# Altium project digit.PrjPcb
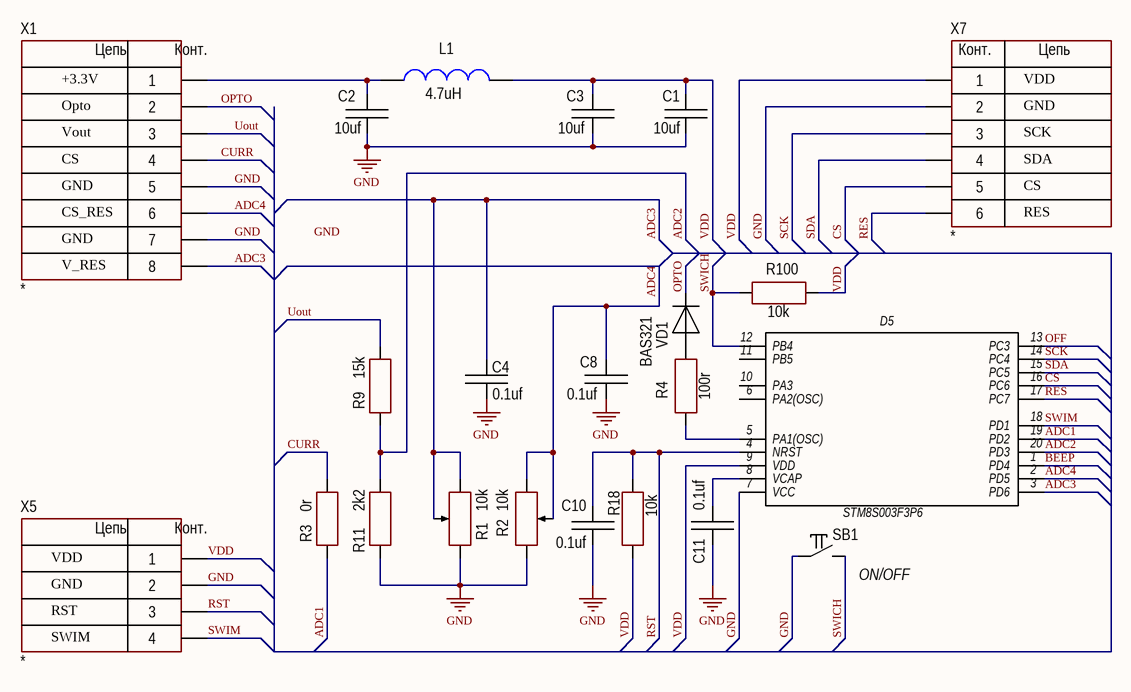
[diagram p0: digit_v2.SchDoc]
2 sheets, 25 parts. Net scope: global (net labels, ports and power ports of the same name join across sheets).
Board file: LCD.PcbDoc
Sheets:
  digit_v2.SchDoc
  LCD.SchDoc

## Sheet digit_v2.SchDoc
size 297 x 209 mm; Address1: Address1; Address2: Address2; Address3: Address3; Address4: Address4; DocumentNumber: АБВГ.123456.001 Э3; SheetNumber: 1; Scale: 1:1; DocumentType: Схема электрическая принципиальная; FirstReferrence: АБВГ.123456.001

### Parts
C1  10uf  [CH1206C]
C2  10uf  [CH1206C]
C3  10uf  [CH1206C]
C4  0.1uf  [CH0805C]
C8  0.1uf  [CH0805C]
C10  0.1uf  [CH0805C]
C11  0.1uf  [CH0805C]
D5  STM8S003F3P6  [20-TSSOP]
L1  4.7uH  [CH1210C]
R1  10k  [Pot-PL-23mm]
R2  10k  [Pot-PL-23mm]
R3  0r  [CH1206R]
R4  100r  [CH0805R]
R9  15k  [CH0805R]
R11  2k2  [CH0805R]
R18  10k  [CH0805R]
R100  10k  [CH0805R]
SB1  ON/OFF  [BUT: 6x6]
VD1  BAS321  [SOD323]
X1  *  [CON: PLS-8]
X5  *  [CON: PLS-4]
X7  *  [CON: PLS-6]

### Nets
GND: C1.1 C2.1 C3.1 C4.2 C8.2 C10.2 C11.2 D5.7(VCC) R1.1 R2.3 R11.1 SB1.1 X1.5 X1.7 X5.2 X7.2
ADC1: D5.19(PD2) R3.1
ADC2: D5.20(PD3) R9.1 R11.2
ADC3: C4.1 D5.3(PD6) R1.2 R1.3 X1.8
ADC4: C8.1 D5.2(PD5) R2.1 R2.2 X1.6
BEEP: D5.1(PD4)
CS: D5.16(PC6) X7.5
CURR: R3.2 X1.4
OFF: D5.13(PC3)
OPTO: VD1.2 X1.2
RES: D5.17(PC7) X7.6
RST: C10.1 D5.4(NRST) R18.2 X5.3
SCK: D5.14(PC4) X7.3
SDA: D5.15(PC5) X7.4
SWICH: D5.12(PB4) R100.1 SB1.2
SWIM: D5.18(PD1) X5.4
Uout: R9.2 X1.3
VDD: C1.2 C3.2 D5.9(VDD) L1.1 R18.1 R100.2 X5.1 X7.1
NetC2_2: C2.2 L1.2 X1.1
NetC11_1: C11.1 D5.8(VCAP)
NetD5_5: D5.5(PA1(OSC)) R4.1
NetR4_2: R4.2 VD1.1

Not connected (* = marked no-connect by the designer): D5 6(PA2(OSC)) 10(PA3) 11(PB5)

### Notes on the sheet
- +3.3V
- VDD
- Vout
- Opto
- SCK
- GND
- CS_RES
- CS
- RES
- SDA
- V_RES
- RST
- SWIM
- Labels drawn without touching a wire or pin: GND

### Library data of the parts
C1-C4 C8 C10 C11 = Capacitor
D5 = STM8S103F3P6
L1 = Inductor
R1 R2 = ADJ resistor
R3 R4 R9 R11 R18 R100 = Resistor
SB1 = Tactile switches: 6x6 mm
VD1 = Diod
X1 = 8-Connector
X5 = 4-Connector
X7 = 6-Connector

## Sheet LCD.SchDoc
size 297 x 209 mm; Address1: Address1; Address2: Address2; Address3: Address3; Address4: Address4; DocumentNumber: АБВГ.123456.001 Э3; SheetNumber: 1; Scale: 1:1; DocumentType: Схема электрическая принципиальная; FirstReferrence: АБВГ.123456.001
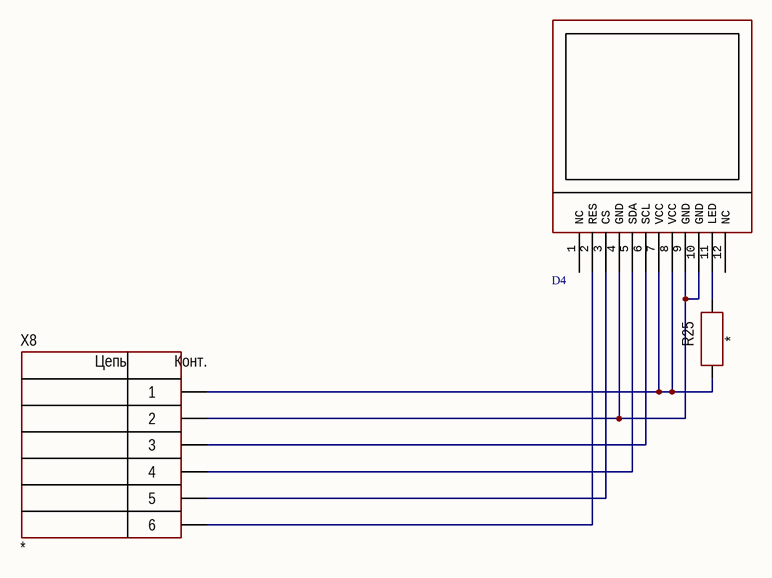
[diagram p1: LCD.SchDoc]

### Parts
D4  Nokia_1616  [LCD1616]  (value not drawn)
R25  *  [CH0805R]
X8  *  [CON: PBS-6]

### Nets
NetD4_2: D4.2(RES) X8.6
NetD4_3: D4.3(CS) X8.5
NetD4_4: D4.4(GND) D4.9(GND) D4.10(GND) X8.2
NetD4_5: D4.5(SDA) X8.4
NetD4_6: D4.6(SCL) X8.3
NetD4_7: D4.7(VCC) D4.8(VCC) R25.1 X8.1
NetD4_11: D4.11(LED) R25.2

Not connected (* = marked no-connect by the designer): D4 1(NC) 12(NC)

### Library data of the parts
D4 = Nokia_1616: MT10-T7
R25 = Resistor
X8 = 6-Connector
